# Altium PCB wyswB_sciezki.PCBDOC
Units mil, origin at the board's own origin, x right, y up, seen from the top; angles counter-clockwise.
Board outline 7130 x 4885 mil, 2 copper layers (Top Layer, Bottom Layer); 18 components, 44 nets, 357 pads, 106 vias.
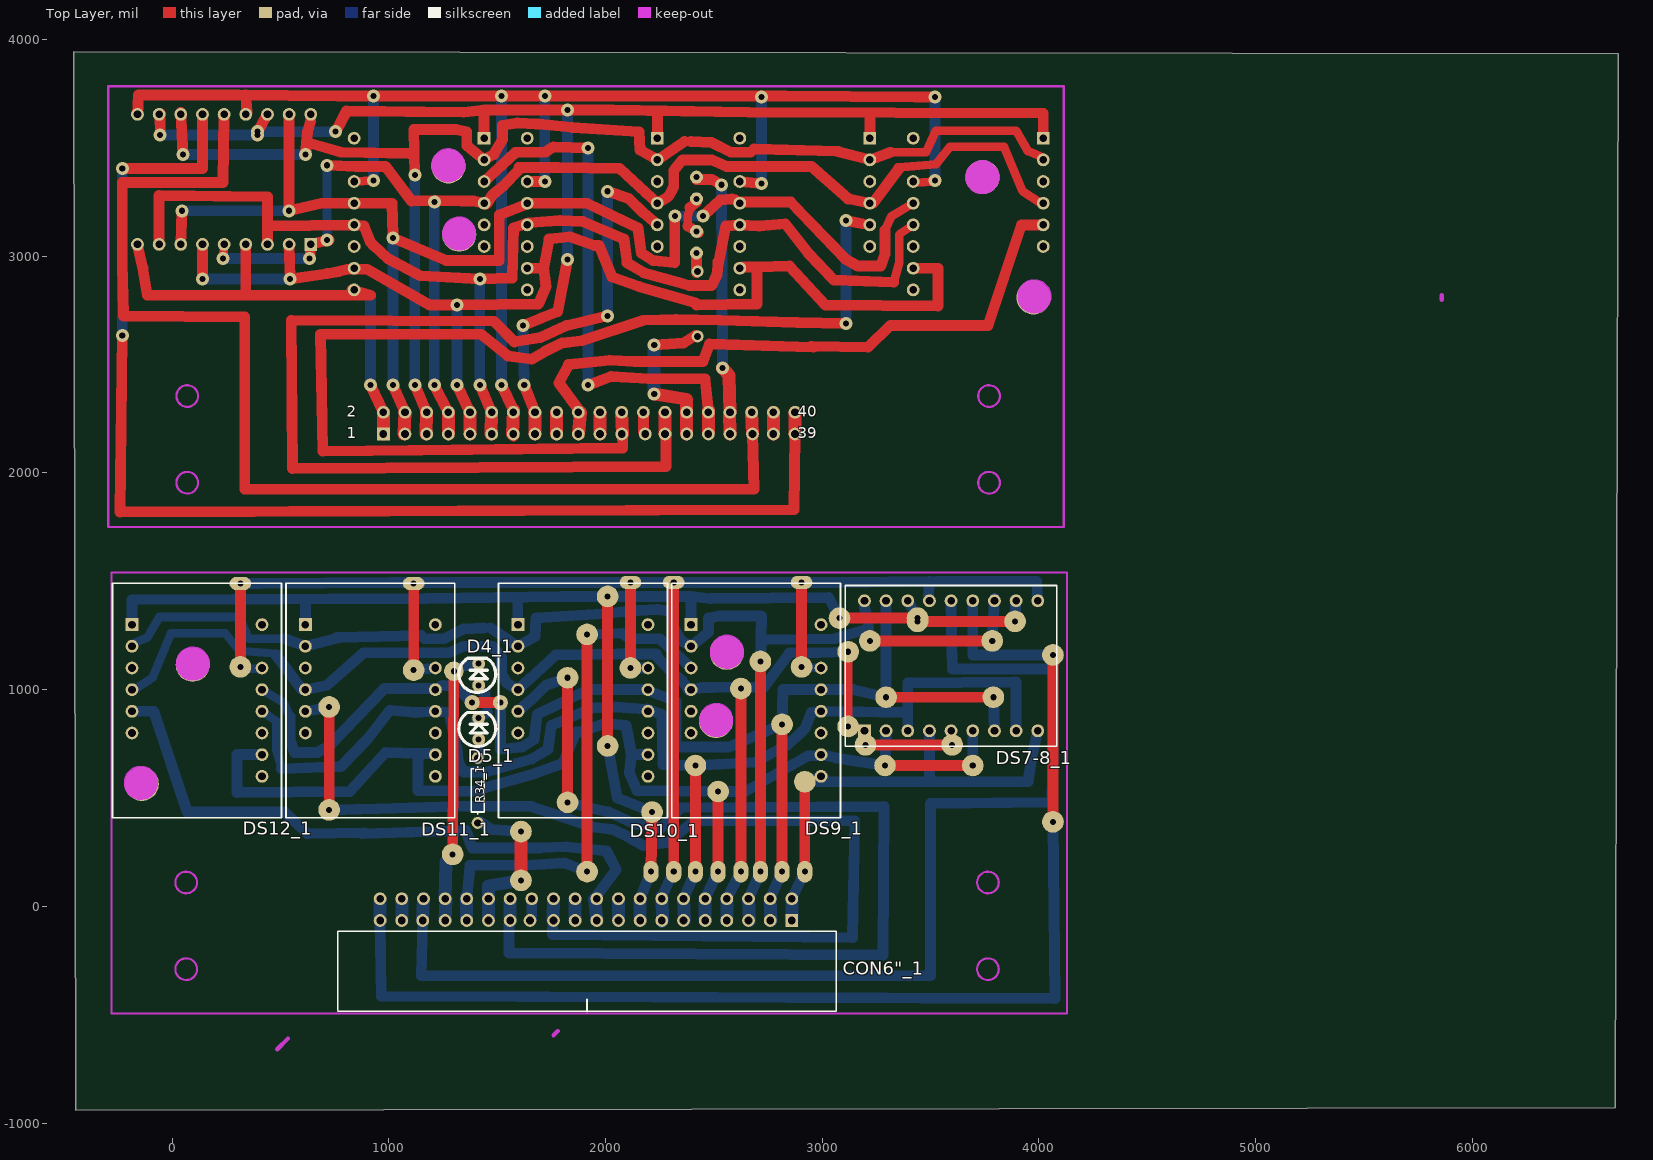
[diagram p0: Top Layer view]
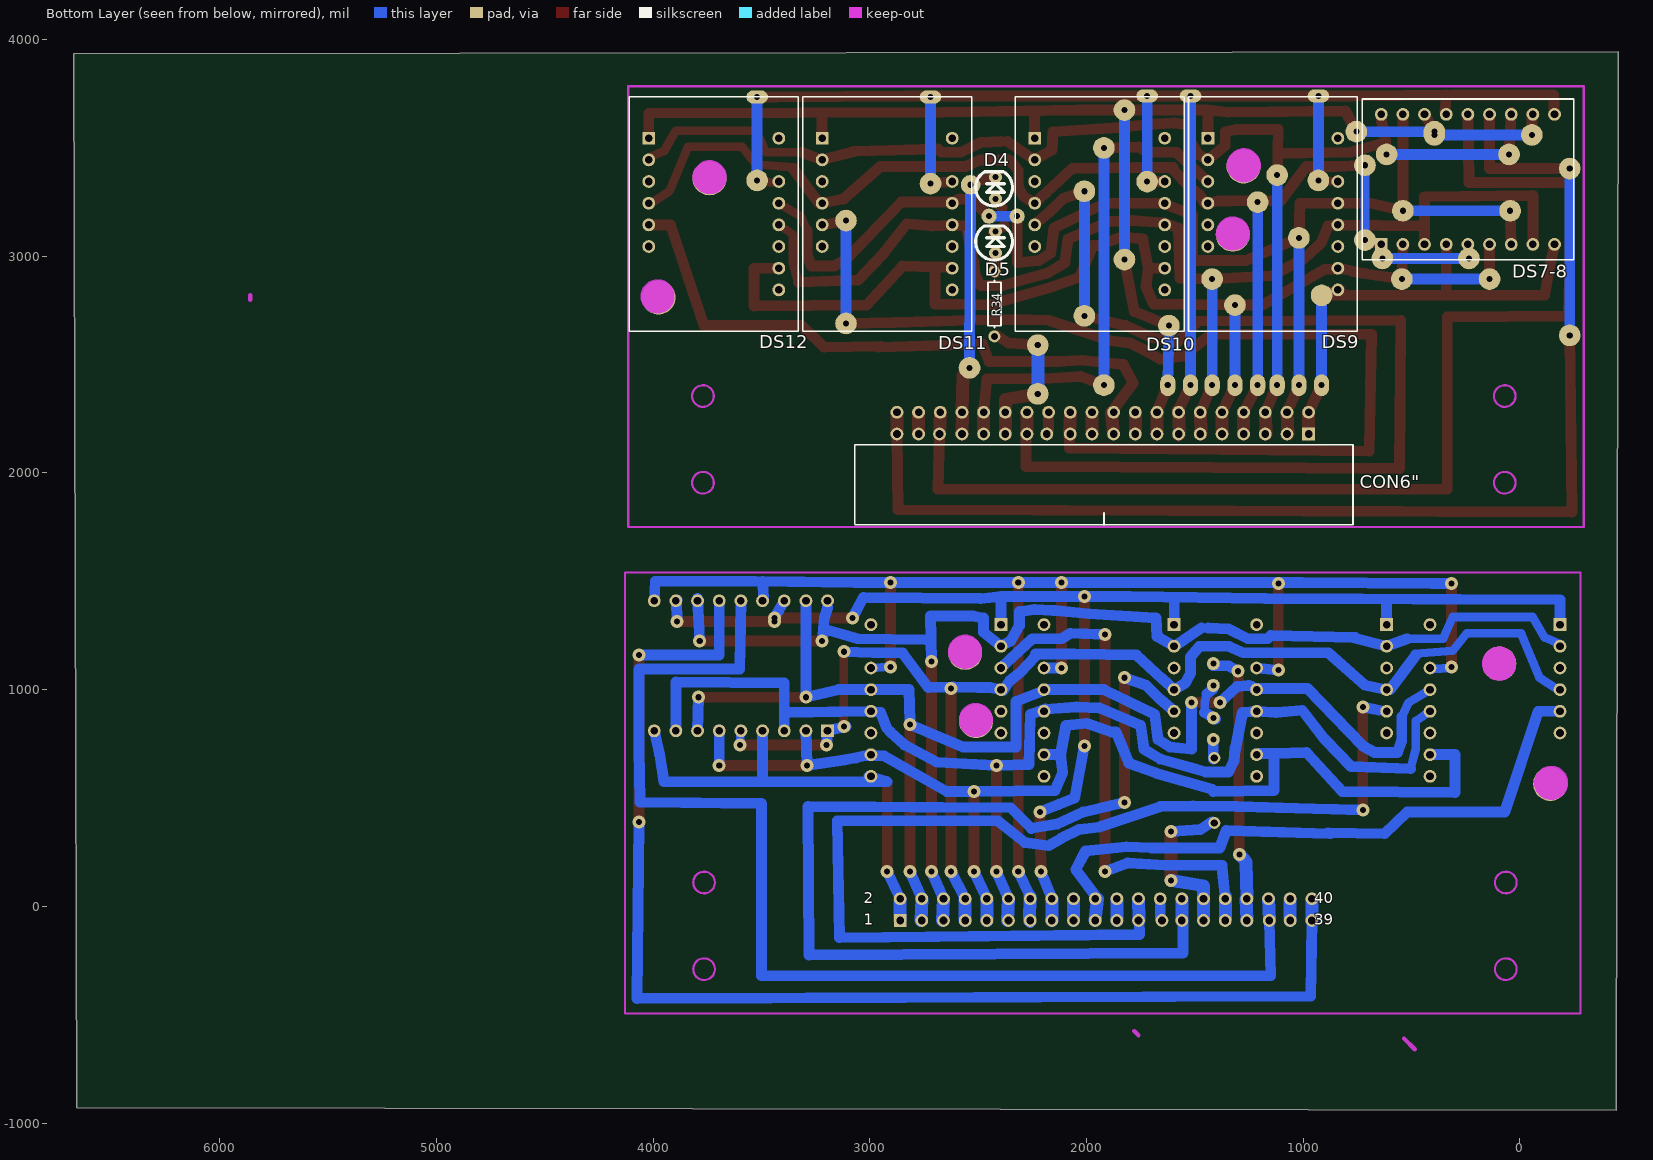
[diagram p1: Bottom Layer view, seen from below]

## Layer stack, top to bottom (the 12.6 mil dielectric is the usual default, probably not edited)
Top Layer: signal copper 1.4
Dielectric: dielectric 12.6, FR-4, Dk 4.8
Bottom Layer: signal copper 1.4

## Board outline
-445,-940 6660,-930 6675,3935 -455,3945

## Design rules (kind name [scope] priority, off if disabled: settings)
Clearance [All] p1: gap=10
ComponentClearance [All] p1: gap=1 collisioncheckmode=0
PolygonConnect [All] p1: connectstyle=Relief reliefconductorwidth=10 reliefentries=4 polygonreliefangle="90 Angle"
RoutingLayers [All] p1: top layer=Horizontal bottom layer=Vertical
RoutingVias [All] p1: holewidth=28 width=50 viastyle="Through Hole" minholewidth=28 minwidth=50 maxholewidth=28 maxwidth=50
SolderMaskExpansion [All] p1: expansion=4
TestPointUsage [All] p1: valid=0 allowmultiple=FALSE
Testpoint [All] p1: side=15 testpointundercomponent=TRUE minsize=40 maxsize=100 preferedsize=60 minholesize=0 maxholesize=40 preferedholesize=32 testpointgrid=1 style=1023 order=-539222988
Width [All] p1: maxlimit=90 minlimit=10 preferedwidth=10 toplayer_prefwidth=50 bottomlayer_prefwidth=50 minimp=50.000000 maximp=50.000000 favimp=50.000000
16 further rules are at their usual default settings.

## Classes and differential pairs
component class WyswD_01: "CON5\"" "CON6\"" D2 D3 D4 D5 DS1-2 DS3-4 DS5-6 DS7-8 DS9 DS10 DS11 DS12 R33 R34

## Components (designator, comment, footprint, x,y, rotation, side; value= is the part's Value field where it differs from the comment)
"CON6\"" "Header 20X2H" HDR2X20_gn_kt 2870,2180 r180 bottom (schematic designator CON6)
"CON6\"_1" "Header 20X2H" HDR2X20_gn_kt 965,-65 r0 top (schematic designator CON6)
D4 "LED_3" LED3 2420,3265 r270 bottom (schematic designator D1)
D4_1 "LED_3" LED3 1415,1020 r270 top (schematic designator D1)
D5 "LED_3" LED3 2420,3015 r270 bottom (schematic designator D2)
D5_1 "LED_3" LED3 1415,770 r270 top (schematic designator D2)
DS7-8 "DA56" LEDDIP-DA/DC56 240,3355 r180 bottom (schematic designator DS12)
DS7-8_1 "DA56" LEDDIP-DA/DC56 3595,1110 r0 top (schematic designator DS12)
DS9 "SA08-11_1" LEDDIP-SA/SC08 1140,3195 r180 bottom (schematic designator DS3)
DS9_1 "SA08-11_1" LEDDIP-SA/SC08 2695,950 r0 top (schematic designator DS3)
DS10 "SA08-11_1" LEDDIP-SA/SC08 1939,3195 r180 bottom (schematic designator DS4)
DS10_1 "SA08-11_1" LEDDIP-SA/SC08 1896,950 r0 top (schematic designator DS4)
DS11 "SA08-11_1" LEDDIP-SA/SC08 2920,3195 r180 bottom (schematic designator DS5)
DS11_1 "SA08-11_1" LEDDIP-SA/SC08 915,950 r0 top (schematic designator DS5)
DS12 "SA08-11_1" LEDDIP-SA/SC08 3720,3195 r180 bottom (schematic designator DS6)
DS12_1 "SA08-11_1" LEDDIP-SA/SC08 115,950 r0 top (schematic designator DS6)
R34 "Res2" AXIAL-0.3 2425,2780 r90 bottom
R34_1 "Res2" AXIAL-0.3 1410,535 r90 top (schematic designator R34)

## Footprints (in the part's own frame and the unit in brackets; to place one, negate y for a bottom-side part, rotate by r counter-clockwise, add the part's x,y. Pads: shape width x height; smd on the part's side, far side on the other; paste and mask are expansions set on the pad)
AXIAL-0.3 [mm]
  round 1.4 hole 0.85: 1(-3.81,0) 2(3.81,0)
  silkscreen extent -2.77,-0.76 2.77,0.76
HDR2X20_gn_kt [mm]
  rect 1.5x1.5 hole 0.9: 1(48.133,0)
  round 1.5 hole 0.9: 2(48.133,2.54) 3(45.593,0) 4(45.593,2.54) 5(43.053,0) 6(43.053,2.54) 7(40.513,0) 8(40.513,2.54) 9(37.973,0) 10(37.973,2.54) 11(35.433,0) 12(35.433,2.54) 13(32.893,0) 14(32.893,2.54) 15(30.353,0) 16(30.353,2.54) 17(27.813,0) 18(27.813,2.54) 19(25.273,0) 20(25.273,2.54) 21(22.733,0) 22(22.733,2.54) 23(20.193,0) 24(20.193,2.54) 25(17.442,0) 26(17.653,2.54) 27(15.113,0) 28(15.113,2.54) 29(12.573,0) 30(12.573,2.54) 31(10.033,0) 32(10.033,2.54) 33(7.493,0) 34(7.493,2.54) 35(4.869,0) 36(4.953,2.54) 37(2.413,0) 38(2.413,2.54) 39(-0.127,0) 40(-0.127,2.54)
  silkscreen extent -5.08,-10.64 53.34,-1.27
LED3 [mil]
  round 60 hole 28: 1(0,0) 2(-100,0)
  silkscreen extent -125,-92 33,78
LEDDIP-DA/DC56 [mm]
  rect 1.5x1.5 hole 0.9: 1(-10.16,-7.62)
  round 1.5 hole 0.9: 2(-7.62,-7.62) 3(-5.08,-7.62) 4(-2.54,-7.62) 5(0,-7.62) 6(2.54,-7.62) 7(5.08,-7.62) 8(7.62,-7.62) 9(10.16,-7.62) 10(10.16,7.62) 11(7.62,7.62) 12(5.08,7.62) 13(2.54,7.62) 14(0,7.62) 15(-2.54,7.62) 16(-5.08,7.62) 17(-7.62,7.62) 18(-10.16,7.62)
  silkscreen extent -12.4,-9.42 12.4,9.43
LEDDIP-SA/SC08 [mm]
  rect 1.5x1.5 hole 0.9: 1(-7.62,8.89)
  round 1.5 hole 0.9: 2(-7.62,6.35) 3(-7.62,3.81) 4(-7.62,1.27) 5(-7.62,-1.27) 6(-7.62,-3.81) 9(7.62,-8.89) 10(7.62,-6.35) 11(7.62,-3.81) 12(7.62,-1.27) 13(7.62,1.27) 14(7.62,3.81) 16(7.62,8.89)
  silkscreen extent -9.9,-13.75 9.9,13.75

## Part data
"CON6\"" "CON6\"_1": "Header, 20-Pin, Dual row, Right Angle"
D4 D4_1 D5 D5_1: "Typical RED, GREEN, YELLOW, AMBER GaAs LED"
DS7-8 DS7-8_1: "Common Anode Dual Seven-Segment Display, Right Hand Decimal"
DS9 DS9_1 DS10 DS10_1 DS11 DS11_1 DS12 DS12_1: "Common Anode Seven-Segment Display, Right Hand Decimal"
R34 R34_1: "Resistor"

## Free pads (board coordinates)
  round 30 on Keep-Out: 0(1185,-580)
  round 157.48 smd: 0(1275,3415) 1(1325,3100) 2(3740,3365) 3(3975,2810) 4(95,1115) 5(2560,1170) 7(2510,855) 8(-140,565)
  round 100 smd: 0(1610,120) 10(315,1105) 11(1115,1090) 12(725,920) 15(725,445) 16(1610,345) 20(1295,240) 24(1825,1055) 26(1825,480) 27(2010,1430) 28(2010,740) 35(2115,1100) 36(2215,435) 40(2415,650) 41(1915,1255) 42(2520,530) 44(2625,1005) 46(2715,1130) 48(2815,840) 51(2920,575) 54(3080,1330) 55(3440,1330) 56(3440,1315) 57(3890,1315) 58(3220,1225) 59(3785,1225) 60(3295,965) 61(3790,965) 62(3200,745) 63(3600,745) 64(3290,650) 65(3695,650) 66(4065,1160) 67(4065,390) 68(1915,160) 69(3120,830) 70(3120,1175) 72(2905,1105)
  round 100 smd far side: 0(2225,2365) 10(3520,3350) 11(2720,3335) 12(3110,3165) 15(3110,2690) 16(2225,2590) 20(2540,2485) 24(2010,3300) 26(2010,2725) 27(1825,3675) 28(1825,2985) 35(1720,3345) 36(1620,2680) 40(1420,2895) 41(1920,3500) 42(1315,2775) 44(1210,3250) 46(1120,3375) 48(1020,3085) 51(915,2820) 54(755,3575) 55(395,3575) 56(395,3560) 57(-55,3560) 58(615,3470) 59(50,3470) 60(540,3210) 61(45,3210) 62(635,2990) 63(235,2990) 64(545,2895) 65(140,2895) 66(-230,3405) 67(-230,2635) 68(1920,2405) 69(715,3075) 70(715,3420) 72(930,3350)
  round 157.48 smd far side: 0(2560,1170) 1(2510,855) 2(95,1120) 3(-140,565) 4(3740,3360) 5(1275,3415) 7(1325,3100) 8(3975,2810)
  oval 100x60 smd: 8(1115,1490) 9(315,1490) 33(2315,1495) 34(2115,1495) 71(2905,1495)
  oval 100x60 smd far side: 8(2720,3735) 9(3520,3735) 33(1520,3740) 34(1720,3740) 71(930,3740)
  round 90 smd: 21(1300,1085)
  round 90 smd far side: 21(2535,3330)
  round 70 smd: 22(1515,940) 23(1385,940)
  round 70 smd far side: 22(2320,3185) 23(2450,3185)
  oval 70x100 smd far side: 37(1625,2405) 38(1520,2405) 39(1420,2405) 43(1315,2405) 45(1210,2405) 47(1120,2405) 49(1020,2405) 50(915,2405)
  oval 70x100 smd: 37(2210,160) 38(2315,160) 39(2415,160) 43(2520,160) 45(2625,160) 47(2715,160) 49(2815,160) 50(2920,160)

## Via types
v1: diameter 60, hole 28, Top Layer to Bottom Layer, 106 vias

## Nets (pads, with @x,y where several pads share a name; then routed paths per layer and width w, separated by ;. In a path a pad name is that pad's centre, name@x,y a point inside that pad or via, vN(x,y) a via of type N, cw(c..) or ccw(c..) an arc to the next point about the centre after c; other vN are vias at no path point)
A: "CON6\".15" "CON6\".16" DS7-8.11 DS7-8.16 DS9.1 DS10.1 DS11.1 DS12.1 pad.27@1825,3675 pad.28@1825,2985 pad.36@1620,2680 pad.37@1625,2405 pad.54@755,3575 pad.55@395,3575 pad.56@395,3560 pad.57@-55,3560 | length 6441.6
  Top Layer w40: v1(395,3560) v1(395,3575)
  Top Layer w50: v1(-55,3560) -56.55,3654.09 DS7-8.11@-55,3660 ; v1(395,3575) DS7-8.16 ; v1(755,3575) 805,3670 1345,3665 1440,3675 ; DS9.1 1440,3675 ; v1(1620,2680) 1705,2715 1780,2745 v1(1825,2985) ; v1(1625,2405) 1675,2280 ; DS10.1@2240,3540 2240,3670 ; DS11.1 3220,3660 ; 4015,3660 2660,3665 2035,3675 1440,3675 ; DS12.1 4020,3660
  Top Layer w60: 1675,2180 1675,2280
  Bottom Layer w50: v1(-55,3560) v1(395,3560) ; v1(395,3575) v1(755,3575) ; v1(1620,2680) v1(1625,2405) ; v1(1825,2985) v1(1825,3675)
"A1\"": 
"A2\"": 
"A3\"": 
"A4\"": 
"A5\"": 
"A6\"": 
A7: "CON6\".39" "CON6\".40" DS7-8.13 pad.66@-230,3405 pad.67@-230,2635 | length 5765.1
  Top Layer w50: v1(-230,2635) -240,1820 2870,1830 2875,2180 ; v1(-230,3405) 140,3405 DS7-8.13
  Top Layer w60: 2875,2180 2875,2280
  Bottom Layer w50: v1(-230,2635) v1(-230,3405)
A8: "CON6\".35" "CON6\".36" DS7-8.14 | length 5445.3
  Top Layer w50: -225,2725 335,2720 335,1925 2685,1925 2678.31,2180 ; -225,2735 -230,2965 -230,3340 235,3340 DS7-8.14
  Top Layer w60: 2675,2280 2678.31,2180
A9: "CON6\".31" "CON6\".32" DS9.3 pad.41@1920,3500 pad.68@1920,2405 | length 2428.8
  Top Layer w50: DS9.3 1585,3480 1720,3480 1760,3505 v1(1920,3500) ; v1(1920,2405) 2025,2445 2200,2435 2290,2435 2460,2435 ; 2460,2425 2475,2280
  Top Layer w60: 2476,2190 2476,2290
  Bottom Layer w50: v1(1920,2405) v1(1920,3500)
A10: "CON6\".27" "CON6\".28" DS10.5 pad.24@2010,3300 pad.26@2010,2725 | length 5031.3
  Top Layer w50: v1(2010,2725) 1820,2680 1700,2625 1580,2605 1485,2700 550,2705 555,2020 2280,2030 2280,2175 ; v1(2010,3300) 2110,3265 2175,3200 DS10.5@2240,3145
  Top Layer w60: 2275,2180 2275,2280
  Bottom Layer w50: v1(2010,2725) v1(2010,3300)
A11: "CON6\".23" "CON6\".24" DS11.5 pad.12@3110,3165 pad.15@3110,2690 | length 5138
  Top Layer w50: 2078.03,2180.09 2080,2115 695,2100 685,2640 1425,2640 1550,2540 1660,2525 1720,2560 1800,2600 1890,2610 2175,2705 2326.71,2708.74 2530,2705 2885,2695 v1(3110,2690) ; v1(3110,3165) 3185,3150
  Top Layer w60: 2075,2280 2078.03,2180.09
  Bottom Layer w50: v1(3110,2690) v1(3110,3165)
A12: "CON6\".19" "CON6\".20" DS12.5 | length 2996.7
  Top Layer w50: 1885,2280 1785,2415 1830,2500 2020,2520 2135,2515 2270,2515 2450,2515 2480,2595 2960,2580 ; 2950,2585 3210,2580 3315,2680 3765,2680 3920,3145 DS12.5
  Top Layer w60: 1875,2180 1885,2280
"A\"": 
B: "CON6\".13" "CON6\".14" DS7-8.10 DS7-8.15 DS9.14 DS10.14 DS11.14 DS12.14 pad.8@2720,3735 pad.9@3520,3735 pad.10@3520,3350 pad.11@2720,3335 pad.33@1520,3740 pad.34@1720,3740 pad.35@1720,3345 pad.38@1520,2405 pad.71@930,3740 pad.72@930,3350 | length 7364.4
  Top Layer w40: DS9.14 v1(930,3350) ; DS12.14@3430,3340 v1@3520,3345
  Top Layer w50: DS7-8.10 -155,3745 305,3745 ; 300,3745 770,3740 ; 340,3745 DS7-8.15@345,3665 ; 765,3740 2145,3740 2830,3740 3430,3735 v1(3520,3735) ; v1(1520,2405) 1575,2290 ; 1571,2180 1575,2170 ; DS10.14@1640,3345 v1(1720,3345) ; DS11.14 v1(2720,3335)
  Top Layer w60: 1571,2180 1575,2290
  Bottom Layer w50: v1(930,3350) v1(930,3740) ; v1(1520,2405) v1(1520,3740) ; pad.35@1720,3350 v1(1720,3740) ; v1(2720,3335) v1(2720,3735) ; v1(3520,3350) v1(3520,3735)
"B\"": 
C: "CON6\".11" "CON6\".12" DS7-8.3 DS7-8.8 DS9.12 DS10.12 DS11.12 DS12.12 pad.39@1420,2405 pad.40@1420,2895 | length 5683.9
  Top Layer w40: 3330,2880 3355,2970 3355,3100 DS12.12
  Top Layer w50: DS7-8.8 -60,3280 440,3275 DS7-8.3 ; 440,3140 DS9.12 885,3140 915,3065 930,3050 995,2990 1145,2910 v1(1420,2895) 1570,2900 1575,3130 DS10.12@1637.4,3152.29 ; v1(1420,2405) 1475,2280 ; 1471,2180 1475,2180 ; DS10.12@1645,3155 1790,3165 1895,3160 2085,3080 2100,2970 2175,2925 2335,2880 2385,2865 2490,2865 2515,2915 2520,2975 ; 2520,2960 2555,3140 DS11.12 ; DS11.12@2615,3145 2710,3140 2830,3150 2935,3015 3055,2890 3330,2880
  Top Layer w60: 1471,2180 1475,2280
  Bottom Layer w50: v1(1420,2405) v1(1420,2895)
"C\"": 
D: "CON6\".9" "CON6\".10" DS7-8.2 DS7-8.6 DS9.10 DS10.10 DS11.10 DS12.10 pad.42@1315,2775 pad.43@1315,2405 pad.64@545,2895 pad.65@140,2895 | length 5453.6
  Top Layer w50: v1(140,2895) DS7-8.6@140,3060 ; DS7-8.2@540,3060 540.15,3055 v1(545,2895) 715,2920 770,2930 810,2940 900,2940 1190,2775 v1(1315,2775) 1690,2780 1725,2860 1715,2945 ; v1(1315,2405) 1375,2280 ; DS10.10@1640,2945 1715,2945 ; 2415,2785 2155,2860 2030,2905 1970,3050 1950,3050 1835,3090 1740,3080 1715,2945 ; 2420,2775 2700,2780 2700,2950 2850,2955 3015,2775 3535,2770 3535,2945 DS12.10 ; DS11.10@2630,2950 2710,2950
  Top Layer w60: 1375,2180 1375,2280
  Bottom Layer w50: v1(140,2895) v1(545,2895) ; v1(1315,2405) v1(1315,2775)
"D\"": 
DP: "CON6\".1" "CON6\".2" DS7-8.4 DS7-8.9 DS9.9 pad.50@915,2405 pad.51@915,2820 | length 2241.6
  Top Layer w50: DS7-8.9 -135,2945 -115,2820 915,2820 DS9.9@830,2845 ; 340,2825 DS7-8.4 ; v1(915,2405) 975,2280
  Top Layer w60: 975,2180 975,2280
  Bottom Layer w50: v1(915,2405) pad.51@915,2820
"DP\"": 
E: "CON6\".7" "CON6\".8" DS7-8.1 DS7-8.5 DS9.4 DS10.4 DS11.4 DS12.4 pad.44@1210,3250 pad.45@1210,2405 pad.62@635,2990 pad.63@235,2990 pad.69@715,3075 pad.70@715,3420 | length 5996.4
  Top Layer w40: v1(235,2990) DS7-8.5 ; 3350,3410 3525,3425 3590,3505 3840,3505 3925,3300 DS12.4@4010,3245
  Top Layer w50: v1(635,2990) DS7-8.1 v1@725,3075 ; v1(715,3420) 850,3415 985,3415 1105,3255 1219.97,3256.77 1335,3255 1390,3255 DS9.4 ; v1(1210,2405) 1275,2280 ; DS9.4@1450,3240 1480,3285 1530,3325 1600,3400 ; 1600,3410 1780,3410 2065,3405 2185,3295 2240,3245 2290,3275 2310,3310 ; 2315,3320 2315,3395 2355,3445 2491.93,3445 2560,3415 ; 2560.84,3415 2950.27,3415 3120,3265 DS11.4 ; DS11.4@3235,3245 3355,3405
  Top Layer w60: 1275,2180 1275,2280
  Bottom Layer w40: v1(715,3075) v1(715,3420)
  Bottom Layer w50: v1(235,2990) v1(635,2990) ; v1(1210,2405) v1(1210,3250)
"E\"": 
F: "CON6\".5" "CON6\".6" DS7-8.12 DS7-8.18 DS9.2 DS10.2 DS11.2 DS12.2 pad.46@1120,3375 pad.47@1120,2405 pad.58@615,3470 pad.59@50,3470 | length 6205.1
  Top Layer w40: 2365,3530 2395,3530 ; 3315,3480 3480,3480 3525,3580 3895,3580 3950,3485 DS12.2@4020,3455
  Top Layer w50: DS7-8.12@40,3665 v1(50,3470) ; 640,3625 625,3575 v1(615,3470) 625,3525 780,3480 1095,3475 ; v1(1120,2405) 1175,2280 ; v1(1120,3375) 1115,3585 1310,3585 1360,3575 1360,3510 DS9.2 1485,3470 1525,3540 1525,3605 1595,3615 1680,3610 ; 1690,3610 1845,3595 2155,3575 2160,3490 ; 2170,3485 2240,3445 2365,3530 ; 2395,3530 2490,3525 2580,3480 ; 2590,3480 2670,3480 ; 2685,3495 3075,3485 ; 3065,3485 DS11.2 3315,3480
  Top Layer w60: 1171,2180 1175,2280
  Bottom Layer w50: v1(50,3470) v1(615,3470) ; v1(1120,2405) v1(1120,3375)
"F\"": 
G: "CON6\".3" "CON6\".4" DS7-8.7 DS7-8.17 DS9.13 DS10.13 DS11.13 DS12.13 pad.22@2320,3185 pad.23@2450,3185 pad.48@1020,3085 pad.49@1020,2405 pad.60@540,3210 pad.61@45,3210 | length 5983.1
  Top Layer w40: 2584.01,3263.86 DS11.13@2600,3265 ; 3290,3120 3320,3185 DS12.13
  Top Layer w50: DS7-8.7 v1(45,3210) ; DS7-8.17 v1(540,3210) 690,3245 DS9.13 1015,3245 v1@1020,3095 ; v1(1020,2405) 1075,2280 ; v1(1020,3085) 1265,2980 1510,2980 1510,3190 1650,3245 1915,3245 2150,3130 2165,3015 2220,2980 2320,2970 v1(2320,3185) ; v1(2450,3185) 2530,3260 2584.01,3263.86 ; DS11.13@2610,3250 2855,3250 3110,2985 3165,2955 3270,2955 3290,3010 3290,3120
  Top Layer w60: 1070,2180 1075,2280
  Bottom Layer w50: v1(45,3210) v1(540,3210) ; v1(1020,2405) v1(1020,3085) ; v1(2320,3185) v1(2450,3185)
"G\"": 
GND: "CON6\".33" "CON6\".34" D4.2 pad.20@2540,2485 pad.21@2535,3330 | length 1285.7
  Top Layer w50: D4.2@2420,3355 2490,3355 v1(2535,3330) ; 2571.93,2279.91 2575,2280
  Top Layer w60: v1(2540,2485) 2570,2450 2575,2280 ; 2571.93,2279.91 2575,2180
  Bottom Layer w50: v1(2535,3330) v1(2540,2485)
"GND\"": 
NC1: "CON6\".37" "CON6\".38" | length 100
  Top Layer w60: 2775,2180 2775,2280
"NC1\"": 
NC2: "CON6\".25" "CON6\".26" | length 91.7
  Top Layer w50: 2175,2188.31 2175,2280
"NC2\"": 
NC3: "CON6\".21" "CON6\".22" | length 100
  Top Layer w60: 1975,2180 1975,2280
"NC3\"": 
NC4: "CON6\".17" "CON6\".18" | length 100
  Top Layer w60: 1775,2180 1775,2280
"NC4\"": 
NetD2_1: 
NetD3_1: 
NetD4_1: D4.1 D5.2 | length 183.6
  Top Layer w40: 2380,3140 2380,3185 2390,3225
  Top Layer w50: 2380,3140 D5.2@2430,3110 ; 2390,3225 D4.1@2420,3250
NetD5_1: D5.1 R34.2 | length 90
  Top Layer w50: R34.2@2420,2925 D5.1
VCC: "CON6\".29" "CON6\".30" pad.0@2225,2365 pad.16@2225,2590 R34.1 | length 737.6
  Top Layer w50: v1(2225,2590) 2360,2600 R34.1@2415,2635
  Top Layer w60: v1(2225,2365) 2375,2340 2375,2280 2375,2180
  Bottom Layer w60: v1(2225,2365) v1(2225,2590)
"VCC\"": 
pads on no net: "CON6\"_1.1" "CON6\"_1.2" "CON6\"_1.3" "CON6\"_1.4" "CON6\"_1.5" "CON6\"_1.6" "CON6\"_1.7" "CON6\"_1.8" "CON6\"_1.9" "CON6\"_1.10" "CON6\"_1.11" "CON6\"_1.12" "CON6\"_1.13" "CON6\"_1.14" "CON6\"_1.15" "CON6\"_1.16" "CON6\"_1.17" "CON6\"_1.18" "CON6\"_1.19" "CON6\"_1.20" "CON6\"_1.21" "CON6\"_1.22" "CON6\"_1.23" "CON6\"_1.24" "CON6\"_1.25" "CON6\"_1.26" "CON6\"_1.27" "CON6\"_1.28" "CON6\"_1.29" "CON6\"_1.30" "CON6\"_1.31" "CON6\"_1.32" "CON6\"_1.33" "CON6\"_1.34" "CON6\"_1.35" "CON6\"_1.36" "CON6\"_1.37" "CON6\"_1.38" "CON6\"_1.39" "CON6\"_1.40" D4_1.1 D4_1.2 D5_1.1 D5_1.2 DS7-8_1.1 DS7-8_1.2 DS7-8_1.3 DS7-8_1.4 DS7-8_1.5 DS7-8_1.6 DS7-8_1.7 DS7-8_1.8 DS7-8_1.9 DS7-8_1.10 DS7-8_1.11 DS7-8_1.12 DS7-8_1.13 DS7-8_1.14 DS7-8_1.15 DS7-8_1.16 DS7-8_1.17 DS7-8_1.18 DS9.5 DS9.6 DS9.11 DS9.16 DS9_1.1 DS9_1.2 DS9_1.3 DS9_1.4 DS9_1.5 DS9_1.6 DS9_1.9 DS9_1.10 DS9_1.11 DS9_1.12 DS9_1.13 DS9_1.14 DS9_1.16 DS10.3 DS10.6 DS10.9 DS10.11 DS10.16 DS10_1.1 DS10_1.2 DS10_1.3 DS10_1.4 DS10_1.5 DS10_1.6 DS10_1.9 DS10_1.10 DS10_1.11 DS10_1.12 DS10_1.13 DS10_1.14 DS10_1.16 DS11.3 DS11.6 DS11.9 DS11.11 DS11.16 DS11_1.1 DS11_1.2 DS11_1.3 DS11_1.4 DS11_1.5 DS11_1.6 DS11_1.9 DS11_1.10 DS11_1.11 DS11_1.12 DS11_1.13 DS11_1.14 DS11_1.16 DS12.3 DS12.6 DS12.9 DS12.11 DS12.16 DS12_1.1 DS12_1.2 DS12_1.3 DS12_1.4 DS12_1.5 DS12_1.6 DS12_1.9 DS12_1.10 DS12_1.11 DS12_1.12 DS12_1.13 DS12_1.14 DS12_1.16 R34_1.1 R34_1.2
copper on no net: | length 74863.5
  Top Layer w40: v1(3120,830) v1(3120,1175)
  Top Layer w50: v1(315,1105) v1(315,1490) ; v1(725,445) v1(725,920) ; v1(1115,1090) v1(1115,1490) ; v1(1295,240) v1(1300,1085) ; v1(1385,940) v1(1515,940) ; v1(1825,480) v1(1825,1055) ; v1(1915,160) v1(1915,1255) ; v1(2010,740) v1(2010,1430) ; v1@2115,1105 v1(2115,1495) ; v1(2210,160) v1(2215,435) ; v1(2315,160) v1(2315,1495) ; v1(2415,160) v1(2415,650) ; v1(2520,160) v1(2520,530) ; v1(2625,160) v1(2625,1005) ; v1(2715,160) v1(2715,1130) ; v1(2815,160) v1(2815,840) ; v1(2905,1105) v1(2905,1495) ; v1(2920,160) 2920,575 ; v1(3080,1330) v1(3440,1330) ; v1(3200,745) v1(3600,745) ; v1(3220,1225) v1(3785,1225) ; v1(3290,650) v1(3695,650) ; v1(3295,965) v1(3790,965) ; v1(3440,1315) v1(3890,1315) ; v1(4065,390) v1(4065,1160)
  Top Layer w60: v1(1610,120) v1(1610,345)
  Bottom Layer w40: -185,1210 -115,1240 -60,1335 310,1335 355,1235 520,1235 ; -175,1000 -90,1055 -5,1260 245,1260 310,1180 485,1165 ; v1@315,1100 405,1095 ; 415,900 480,855 480,725 505,635 ; 415,1000 515,940 545,875 ; 1235,1020 1250.99,1018.86 ; 1440,1285 1470,1285 ; 1445,980 1455,940 1455,895 ; v1(2905,1105) 2995,1100 ; v1(3440,1315) v1(3440,1330) ; 3595,810 v1(3600,745)
  Bottom Layer w50: -185,900 -85,900 70,435 520,435 625,335 885,340 ; -185,1300 -185,1415 ; -180,1415 1175,1420 1800,1430 2395,1430 ; v1(315,1490) 405,1490 1005,1495 1690,1495 3070,1495 ; 415,700 300,700 300,525 820,530 985,710 1135,705 1135,535 1415,530 ; 480,1160 600,1000 ; 505,635 780,645 900,770 1005,905 1125,895 1220,900 ; 520,1235 615,1200 770,1240 ; 545,875 545,765 565,710 670,710 725,740 980,1005 1225,1005 ; 615,1000 715,1020 884.73,1170 1274.16,1170 ; 615,1300 615,1415 ; 650,905 v1(725,920) ; v1(725,445) 950,450 1305,460 1508.29,463.74 1660,460 1945,365 2035,355 2115,315 2175,280 2285,295 2410,395 3150,395 3140,-145 1755,-130 1756.97,-64.91 ; 760,1240 1150,1250 ; 875,335 1355,350 1385,270 1565,270 1700,270 1815,275 2005,255 2050,170 1950,35 ; 960,-65 965,-415 4075,-425 v1(4065,390) ; v1(1115,1090) 1215,1100 ; 1125,705 1205,705 ; 1156.69,-65 1150,-320 3500,-320 3500,475 4060,480 ; 1165,1235 1245,1235 ; 1215,900 1280,895 1315,715 ; 1250.99,1018.86 1305,1015 v1(1385,940) ; 1255,1235 1345,1280 1440,1285 ; 1260,35 1263.07,34.91 ; 1275,1170 1343.07,1200 1480,1200 1520,1150 1520,1075 ; v1(1300,1085) 1345,1110 1415,1110 ; 1315,730 1320,670 1345,620 1450,620 1500,635 1660,680 1735,725 1750,835 1940,915 2045,920 2190,910 ; 1360,35 1375,180 ; 1375,190 1545,190 1635,190 1810,200 v1(1915,160) ; 1405,865 1455,895 ; 1415,680 1415,770 ; 1415,1005 1445,980 ; 1420,390 1475,355 v1(1610,345) ; 1420,540 1680,615 1805,660 1865,805 1885,805 2000,845 2095,835 2120,700 ; 1470,1285 1595,1200 1665,1240 ; v1(1515,940) 1515,725 1615,735 1670,770 1685,885 1920,1000 2185,1000 2325,945 2325,735 2570,735 v1(2815,840) ; 1525,1065 1545,1030 1595,1000 1650,1050 1770,1160 2055,1165 2235,1165 ; 1555,-70 1555,-215 3280,-225 3285,460 2350,455 2255,360 2135,380 2015,435 v1(1825,480) ; 1595,900 1660,955 1725,1020 v1(1825,1055) ; 1595,1295 1595,1425 ; 1660,-56.69 1660,35 ; 1675,1245 1680,1330 1990,1350 2145,1365 ; v1(1915,1255) 2075,1260 2115,1235 2250,1235 2395,1100 ; v1(2010,740) 2055,500 2130,470 v1(2215,435) ; v1(2115,1100) 2195,1100 ; 2155,1365 2240,1370 2310,1360 2310,1295 2350,1225 2395,1200 2475,1265 2475,1330 2525,1340 2720,1340 v1(2715,1130) ; 2160,35 v1(2210,160) ; 2195,700 2120,700 ; 2197.6,907.29 2260,885 2265,655 v1(2415,650) 2690,665 2840,745 2905,805 2920,820 2950,895 2995,900 3395,895 ; 2235,1155 2305,1080 2355,1040 2385,995 ; 2260,-75 2264,-65 ; 2260,45 v1(2315,160) ; 2360,-65 2364,-65 ; 2360,35 v1(2415,160) ; 2395,1000 2445,1010 2500,1010 2615.03,1011.77 2730,1010 2850,1170 2985,1170 v1(3120,1175) ; 2395,1300 2395,1430 ; 2460,35 v1(2520,160) ; 2560,35 v1(2625,160) ; 2660,35 v1(2715,160) ; 2740,1230 3055,1235 3210,1280 v1(3220,1225) 3210,1330 3195,1380 ; 2760,35 v1(2815,160) ; v1@2815,850 2820,1000 2995,1000 3145,1000 v1(3295,965) 3295,1410 ; 2860,35 v1(2920,160) ; 3005,600 2920,575 3950,575 3970,700 3995,810 ; 3065,1495 3535,1500 ; v1(3080,1330) 3030,1425 2490,1420 2395,1430 ; v1@3110,830 3195,810 v1(3200,745) ; 3295,815 3294.85,810 v1(3290,650) 3120,675 3065,685 3025,695 2935,695 2645,530 v1(2520,530) 2145,535 2110,615 2120,700 ; 3395,810 3395,1030 3895,1035 3895,810 ; 3395,1410 v1(3440,1330) ; 3490,1420 3495,1500 ; 3495,580 3495,810 ; 3530,1500 3990,1500 3995,1410 ; 3595,1410 3600,1095 4065,1095 4065,720 4060,490 ; v1(3695,650) 3695,815 ; 3695,1410 3695,1160 v1(4065,1160) ; v1(3785,1225) 3795,1420 ; v1(3790,965) 3795,810 ; v1(3890,1315) 3891.55,1409.09 3890,1415
  Bottom Layer w60: 960,-65 960,35 ; 1060,-65 1060,35 ; 1156.69,-65 1160,35 ; 1260,-65 1263.07,34.9 ; 1260,35 1265,205 v1(1295,240) ; 1359,-55 1359,45 ; 1460,-65 1460,35 1460,95 v1(1610,120) ; 1560,-65 1560,35 ; 1756.97,-64.91 1760,35 ; 1860,-65 1860,35 ; 1950,35 1960,-65 ; 2060,-65 2060,35 ; 2160,-65 2160,35 ; 2260,45 2264,-65 ; 2360,35 2364,-65 ; 2460,-65 2460,35 ; 2560,-65 2560,35 ; 2660,35 2664,-65 ; 2760,35 2765,-65 ; 2860,-65 2860,35

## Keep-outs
Keep-Out Layer:
  circle w78.74: c1324.37,3105 r39.37
  circle w78.74: c1274.37,3420 r39.37
  circle w78.74: c3979.37,2815 r39.37
  circle w78.74: c3739.37,3365 r39.37
  circle w10: c70,2355 r50
  circle w10: c70,1955 r50
  circle w10: c3770,2355 r50
  circle w10: c3770,1955 r50
  circle w78.74: c2510.63,860 r39.37
  circle w78.74: c2560.63,1175 r39.37
  circle w78.74: c-144.37,570 r39.37
  circle w78.74: c95.63,1120 r39.37
  circle w10: c3765,110 r50
  circle w10: c3765,-290 r50
  circle w10: c65,110 r50
  circle w10: c65,-290 r50
  lines w10: -295,1750 -295,3785 4115,3785 4115,1750 -295,1750 ; -280,-495 -280,1540 4130,1540 4130,-495 -280,-495
  lines w20: 485,-660 535,-610 ; 1760,-595 1780,-575 ; 5860,2800 5860,2820
  text "wysw_B strona elementow" at 4205,2705 h100
  text "wysw_B strona lutowania" at 4235,645 h100
  text "Rys.10 Uklad sciezek wyswietlacza B" at -300,-700 h120

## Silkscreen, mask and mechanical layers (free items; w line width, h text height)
Mechanical 4:
  lines w10: -280,2150 -275,2155 ; -205,0 -200,5 ; 4110,-90 4115,-95
  lines w30: -285,-485 415,-485 415,305 -285,305 -285,-485 ; -285,1760 415,1760 415,2550 -285,2550 -285,1760 ; 3420,-485 4120,-485 4120,305 3420,305 3420,-485 ; 3420,1760 4120,1760 4120,2550 3420,2550 3420,1760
